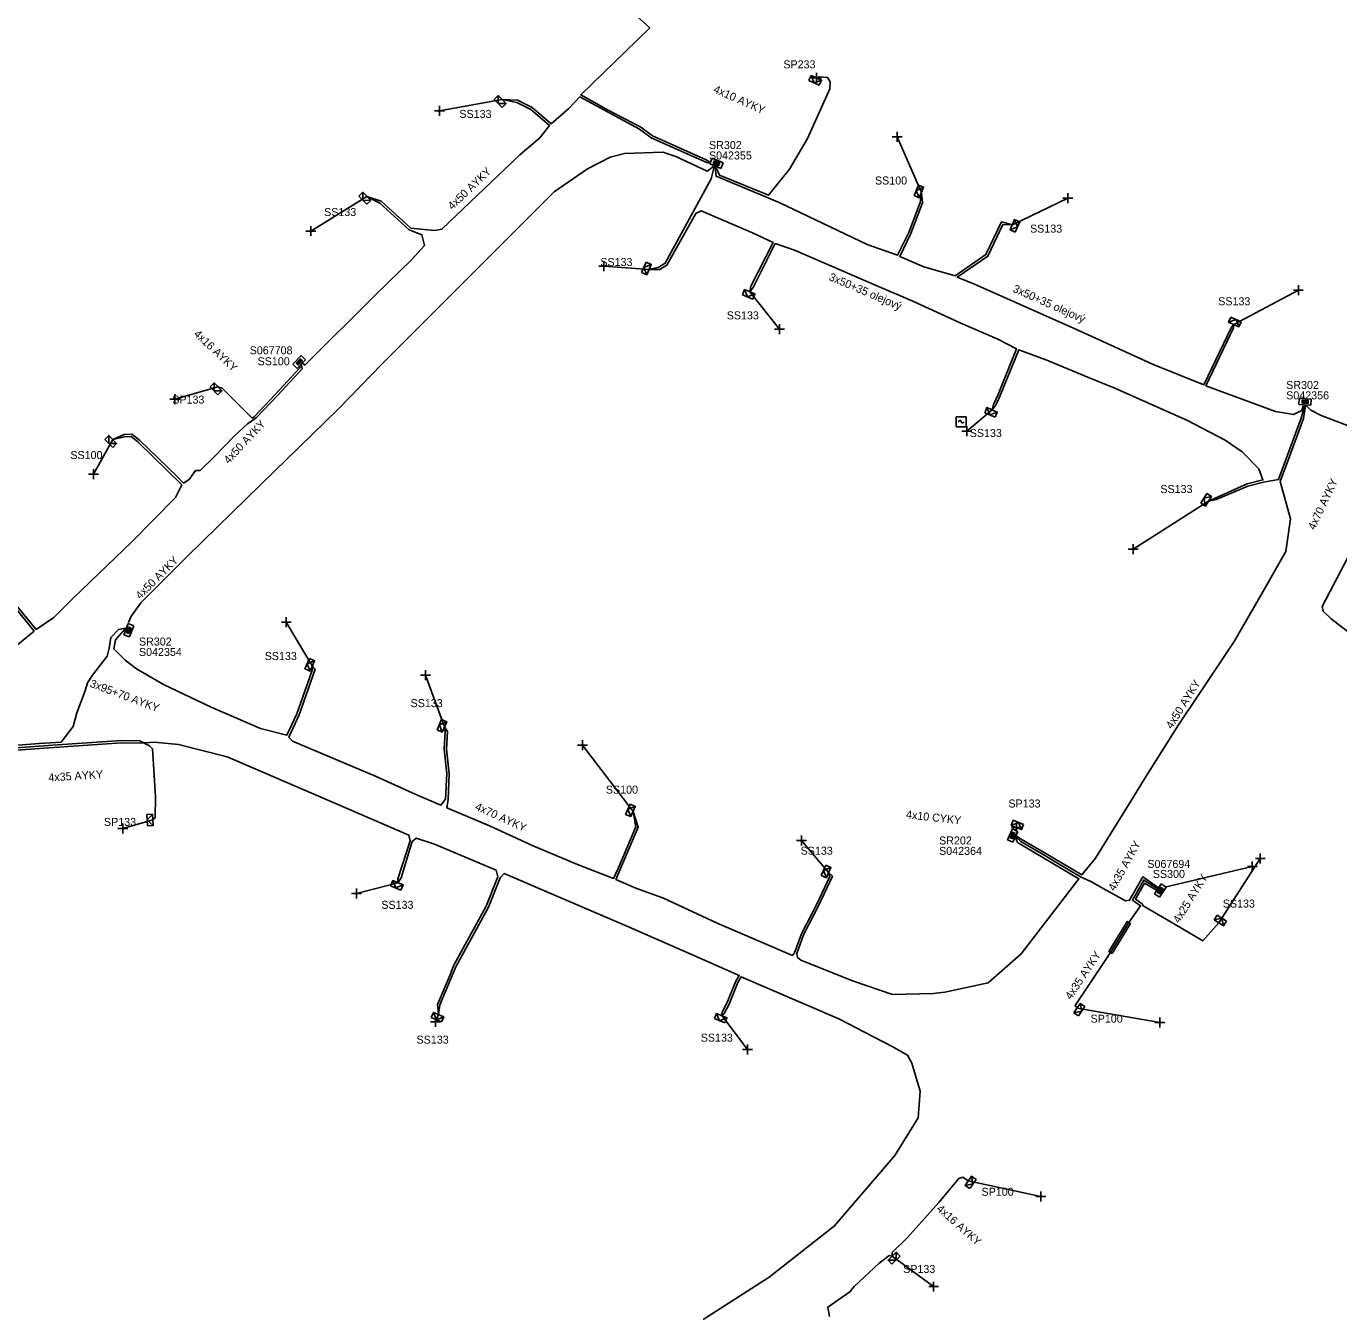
# Model space of a CAD drawing. Extents: x -748492 to -735633, y -1146251 to -1139940.
# Drawn here: x -736525.5 to -736361.6, y -1144461 to -1144300.4 of the extents above; entities that cross this region are included whole.
import ezdxf

# ---------------------------------------------------------------- set-up
doc = ezdxf.new("R2010")
doc.units = 0
for name, color, linetype in [('Vrstva 1', 7, 'Continuous'), ('Vrstva 20', 7, 'Continuous'), ('Vrstva 28', 7, 'Continuous'), ('Vrstva 29', 7, 'Continuous'), ('Vrstva 30', 7, 'Continuous'), ('Vrstva 31', 7, 'Continuous'), ('Vrstva 33', 7, 'Continuous'), ('Vrstva 34', 7, 'Continuous'), ('Vrstva 5', 7, 'Continuous'), ('Vrstva 52', 7, 'Continuous'), ('Vrstva 54', 7, 'Continuous'), ('Vrstva 59', 7, 'Continuous'), ('Vrstva 6', 7, 'Continuous'), ('Vrstva 8', 7, 'Continuous'), ('Vrstva 9', 7, 'Continuous')]:
    doc.layers.add(name, color=color, linetype=linetype)

# ---------------------------------------------------------------- blocks, each defined once
blk = doc.blocks.new('NN800')
at = {"layer": 'Vrstva 1'}
for points in [[(-0.44, 0.44), (0.44, -0.44)], [(-0.44, -0.44), (0.44, 0.44)]]:
    blk.add_lwpolyline(points, dxfattribs=at)
blk = doc.blocks.new('NN620')
at = {"layer": 'Vrstva 8'}
for points in [[(0.75, 0), (-0.75, 0)], [(-0.75, 0), (-0.75, -0.75)], [(0.75, -0.75), (0.75, 0)], [(-0.75, -0.75), (0.75, -0.75)], [(0.37, -0.18), (-0.38, -0.18)], [(-0.38, -0.18), (-0.38, -0.56)], [(-0.38, -0.56), (0.37, -0.56)], [(0.32, -0.23), (-0.33, -0.23)], [(-0.33, -0.23), (-0.33, -0.51)], [(-0.33, -0.51), (0.32, -0.51)], [(0.27, -0.27), (-0.28, -0.27)], [(-0.28, -0.27), (-0.28, -0.46)], [(-0.28, -0.46), (0.27, -0.46)], [(0.23, -0.32), (-0.23, -0.32)], [(-0.23, -0.32), (-0.23, -0.42)], [(-0.23, -0.42), (0.23, -0.42)], [(-0.19, -0.37), (0.19, -0.37)], [(0.23, -0.42), (0.23, -0.32)], [(0.27, -0.46), (0.27, -0.27)], [(0.32, -0.51), (0.32, -0.23)], [(0.37, -0.56), (0.37, -0.18)]]:
    blk.add_lwpolyline(points, dxfattribs=at)
blk = doc.blocks.new('NN630')
at = {"layer": 'Vrstva 9'}
for points in [[(0, -0.7), (-0.7, 0)], [(-0.7, -0.7), (-0.7, 0), (0.7, 0), (0.7, -0.7)], [(-0.7, -0.7), (0.7, -0.7)], [(0, -0.7), (0.7, 0)]]:
    blk.add_lwpolyline(points, dxfattribs=at)
blk = doc.blocks.new('NN740')
at = {"layer": 'Vrstva 1'}
for points in [[(0.62, 0.62), (-0.63, 0.62)], [(-0.63, 0.62), (-0.63, -0.63)], [(0, 0), (0, 0.01), (0, 0.03), (-0.01, 0.05), (-0.01, 0.06), (-0.02, 0.08), (-0.03, 0.09), (-0.04, 0.1), (-0.05, 0.11), (-0.06, 0.12), (-0.08, 0.13), (-0.09, 0.14), (-0.11, 0.14), (-0.12, 0.15), (-0.14, 0.15), (-0.15, 0.15), (-0.17, 0.15), (-0.18, 0.15), (-0.2, 0.15), (-0.21, 0.14), (-0.23, 0.13), (-0.24, 0.12), (-0.26, 0.11), (-0.27, 0.1), (-0.28, 0.09), (-0.29, 0.08), (-0.29, 0.06), (-0.3, 0.05), (-0.3, 0.03), (-0.31, 0.02), (-0.31, 0), (-0.31, 0)], [(0.62, -0.63), (0.62, 0.62)], [(-0.63, -0.63), (0.62, -0.63)], [(0, 0), (0, -0.02), (0, -0.03), (0.01, -0.05), (0.01, -0.06), (0.02, -0.08), (0.03, -0.09), (0.04, -0.1), (0.05, -0.11), (0.06, -0.12), (0.07, -0.13), (0.09, -0.14), (0.1, -0.15), (0.12, -0.15), (0.13, -0.15), (0.15, -0.15), (0.16, -0.15), (0.18, -0.15), (0.19, -0.15), (0.21, -0.14), (0.22, -0.14), (0.24, -0.13), (0.25, -0.12), (0.26, -0.11), (0.27, -0.09), (0.28, -0.08), (0.29, -0.07), (0.29, -0.05), (0.3, -0.04), (0.3, -0.02), (0.3, -0.01), (0.3, -0.01)]]:
    blk.add_lwpolyline(points, dxfattribs=at)

msp = doc.modelspace()

# ---------------------------------------------------------------- linework, layer by layer
at = {"layer": 'Vrstva 20'}
msp.add_lwpolyline([(-736389.88, -1144416.27), (-736390.3, -1144416.01), (-736388.01, -1144412.26), (-736387.59, -1144412.52)], close=True, dxfattribs=at)
at = {"layer": 'Vrstva 5'}
for points in [[(-736440.21, -1144317.36), (-736440.6, -1144317.09), (-736447.33, -1144314.09), (-736448.79, -1144313.02), (-736452.94, -1144310.85), (-736456.27, -1144308.99), (-736450.7, -1144303.56), (-736447.65, -1144300.62), (-736452.08, -1144296.64)], [(-736491.06, -1144342.47), (-736490.75, -1144342.74), (-736481.89, -1144333.95), (-736477.42, -1144329.58), (-736475.81, -1144327.82), (-736476.12, -1144326.48), (-736477.71, -1144325.85), (-736481.37, -1144322.52), (-736483, -1144321.67), (-736481.21, -1144322.26), (-736477.51, -1144325.63), (-736474.55, -1144325.92), (-736473.63, -1144325.79), (-736463.89, -1144316.47), (-736461.38, -1144314.35), (-736460.17, -1144312.82), (-736462.51, -1144310.83), (-736464.27, -1144309.96), (-736466.1, -1144309.57), (-736464.19, -1144309.66), (-736462.35, -1144310.57), (-736459.97, -1144312.6), (-736457.75, -1144310.68), (-736456.41, -1144309.25), (-736448.95, -1144313.28), (-736447.49, -1144314.35), (-736440.74, -1144317.35), (-736440.29, -1144317.54)], [(-736439.71, -1144317.93), (-736440.5, -1144318.51), (-736444.39, -1144316.69), (-736446.01, -1144316.16), (-736450.82, -1144316.33), (-736452.62, -1144316.77), (-736455.42, -1144318.25), (-736459.6, -1144321.09), (-736467.51, -1144329.02), (-736481.04, -1144342.55), (-736486.6, -1144348.27), (-736496.25, -1144357.68), (-736505.35, -1144366.59), (-736511.22, -1144372.44), (-736512.5, -1144374.21), (-736512.77, -1144374.92)], [(-736439.59, -1144317.99), (-736439.99, -1144319.5), (-736445.73, -1144330.03), (-736446.51, -1144330.52), (-736447.75, -1144330.82), (-736446.41, -1144330.8), (-736445.51, -1144330.25), (-736441.89, -1144323.81), (-736441.25, -1144323.47), (-736434.82, -1144326.24), (-736432.24, -1144327.43), (-736435.02, -1144332.87), (-736435.17, -1144333.59), (-736434.7, -1144332.99), (-736431.98, -1144327.57), (-736429.56, -1144328.39), (-736419.36, -1144332.81), (-736414.8, -1144334.76), (-736408.79, -1144337.53), (-736404.19, -1144339.51), (-736401.85, -1144340.71), (-736404.15, -1144346.43), (-736404.72, -1144347.67), (-736404.89, -1144348.34), (-736404.37, -1144347.66), (-736403.87, -1144346.55), (-736401.57, -1144340.83), (-736398.06, -1144342.15), (-736392.85, -1144344.32), (-736389.55, -1144345.65), (-736380.49, -1144349.68), (-736375.78, -1144352.14), (-736373.64, -1144353.6), (-736371.56, -1144355.73), (-736371.06, -1144357.09), (-736373.04, -1144357.59), (-736377.84, -1144359.77), (-736376.88, -1144359.54), (-736372.94, -1144357.87), (-736370.98, -1144357.39), (-736369.11, -1144357.06), (-736366.28, -1144349.39), (-736365.88, -1144347.85)], [(-736439.47, -1144318.04), (-736439.37, -1144319.16), (-736431.51, -1144322.44), (-736420.48, -1144327.7), (-736416.69, -1144329.03), (-736415.31, -1144326.2), (-736413.87, -1144322.42), (-736413.72, -1144321.19), (-736413.57, -1144322.48), (-736415.03, -1144326.32), (-736416.42, -1144329.17), (-736413.43, -1144330.46), (-736409.5, -1144331.59), (-736405.66, -1144328.95), (-736403.72, -1144324.87), (-736402.36, -1144325.21), (-736403.54, -1144325.19), (-736405.42, -1144329.15), (-736409.24, -1144331.77), (-736407.08, -1144332.65), (-736394.34, -1144338.32), (-736384.87, -1144342.64), (-736378.44, -1144345.2), (-736374.99, -1144338.03), (-736374.7, -1144337.68), (-736374.74, -1144338.11), (-736378.18, -1144345.34), (-736369.48, -1144348.55), (-736367.25, -1144348.92), (-736366.18, -1144348.42), (-736366.01, -1144347.84)], [(-736514.75, -1144352.04), (-736513.33, -1144351.43), (-736512.34, -1144351.39), (-736511.41, -1144352.12), (-736506.69, -1144356.65), (-736505.9, -1144357.5), (-736505.21, -1144357.04), (-736504.4, -1144355.92), (-736503.83, -1144355.9), (-736502.16, -1144354.28), (-736499.49, -1144351.56), (-736497.89, -1144350.1), (-736496.82, -1144349.36), (-736494.14, -1144346.49), (-736491.06, -1144343.22), (-736491.19, -1144342.63)], [(-736401.82, -1144401.62), (-736401.26, -1144401.96), (-736398.16, -1144403.77), (-736393.68, -1144406.44), (-736391.97, -1144404.35), (-736387.56, -1144397.22), (-736385.84, -1144394.45), (-736381.61, -1144387.69), (-736378.96, -1144383.76), (-736374.64, -1144377.3), (-736371.56, -1144371.96), (-736368.18, -1144366.03), (-736367.61, -1144361.94), (-736368.91, -1144357.3), (-736367.84, -1144354.5), (-736365.98, -1144349.43), (-736365.75, -1144347.85)], [(-736365.62, -1144347.86), (-736365.07, -1144348.39), (-736363.8, -1144349.06), (-736359.62, -1144350.63), (-736354.85, -1144352.88), (-736353.13, -1144352.91), (-736352.44, -1144352.02), (-736351.83, -1144350.9), (-736350.53, -1144349.56), (-736349.96, -1144349.5)], [(-736526.82, -1144372.73), (-736524.33, -1144375.78), (-736522.1, -1144374.28), (-736519.75, -1144371.93), (-736512.32, -1144364.8), (-736506.91, -1144359.28), (-736506.12, -1144357.7), (-736511.61, -1144352.34), (-736512.44, -1144351.69), (-736513.27, -1144351.73), (-736514.75, -1144352.04)], [(-736528.43, -1144379.15), (-736524.57, -1144375.98), (-736527.01, -1144372.97)], [(-736513.19, -1144375.63), (-736514.02, -1144375.78), (-736514.97, -1144376.79), (-736515.21, -1144378.1), (-736515.44, -1144379.11), (-736517.28, -1144381.47), (-736517.9, -1144382.45), (-736518.19, -1144383.45), (-736519.23, -1144386.21), (-736519.68, -1144387.88), (-736521.2, -1144389.86), (-736523.95, -1144390.03), (-736529.77, -1144390.49), (-736531.34, -1144391.33), (-736533.26, -1144392.69), (-736535.8, -1144394.49), (-736538.4, -1144396.09), (-736545.61, -1144401.24), (-736547.24, -1144402.4), (-736548.21, -1144402.26), (-736548.67, -1144401.65), (-736551.08, -1144398), (-736551.94, -1144397.36)], [(-736513.23, -1144375.75), (-736514.41, -1144377.07), (-736514.62, -1144378.21), (-736513.18, -1144379.6), (-736511.77, -1144380.69), (-736508.41, -1144382.64), (-736502.44, -1144385.48), (-736496.3, -1144388.13), (-736492.98, -1144388.98), (-736491.75, -1144386.33), (-736490.5, -1144382.77), (-736489.78, -1144380.74), (-736489.81, -1144380.33), (-736489.46, -1144380.72), (-736491.47, -1144386.45), (-736492.76, -1144389.25), (-736492.28, -1144389.72), (-736481.83, -1144394.16), (-736476.87, -1144396.39), (-736473.74, -1144397.73), (-736473.16, -1144396.99), (-736473.01, -1144393.77), (-736473.33, -1144390.75), (-736473.22, -1144388.57), (-736473.3, -1144387.95), (-736472.92, -1144388.53), (-736473.03, -1144390.75), (-736472.71, -1144393.77), (-736472.86, -1144397.01), (-736473.01, -1144398.06), (-736467.66, -1144400.32), (-736462.13, -1144402.85), (-736456.69, -1144405.13), (-736452.18, -1144406.88), (-736451.59, -1144405.66), (-736449.41, -1144400.45), (-736449.75, -1144398.52), (-736449.09, -1144400.47), (-736451.88, -1144407), (-736449.39, -1144408.11), (-736445.96, -1144409.34), (-736439.23, -1144412.46), (-736429.84, -1144416.49), (-736429.56, -1144416.16), (-736428.71, -1144413.8), (-736426.84, -1144410.17), (-736425.15, -1144406.63), (-736425.31, -1144406.15), (-736424.81, -1144406.61), (-736426.58, -1144410.31), (-736428.43, -1144413.92), (-736429.28, -1144416.26), (-736429.18, -1144416.77), (-736428.77, -1144417.09), (-736422.19, -1144419.73), (-736417.34, -1144421.39), (-736412.25, -1144421.25), (-736410.79, -1144421.08), (-736405.37, -1144419.91), (-736401.25, -1144416.31), (-736394.05, -1144406.92), (-736401.7, -1144402.38), (-736401.93, -1144401.85)], [(-736529.6, -1144391.08), (-736523.91, -1144390.63), (-736519.08, -1144390.33), (-736513.63, -1144389.94), (-736511.36, -1144389.99), (-736509.56, -1144389.86), (-736506.52, -1144390.14), (-736500.44, -1144391.68), (-736486.98, -1144397.48), (-736477.75, -1144401.47), (-736477.6, -1144402.19), (-736479.11, -1144406.92), (-736479.12, -1144407.42), (-736478.73, -1144406.82), (-736477.32, -1144402.27), (-736476.83, -1144401.84), (-736474.53, -1144402.6), (-736470, -1144404.5), (-736466.83, -1144405.86), (-736466.62, -1144406.67), (-736468.1, -1144410.34), (-736472.16, -1144417.8), (-736472.57, -1144418.92), (-736474.17, -1144422.63), (-736474.03, -1144423.89), (-736473.87, -1144422.69), (-736471.88, -1144417.92), (-736467.82, -1144410.46), (-736466.34, -1144406.79), (-736465.84, -1144406.26), (-736459.35, -1144409.05), (-736450.33, -1144412.94), (-736441.84, -1144416.65), (-736436.48, -1144419), (-736436.91, -1144419.73), (-736438.02, -1144422.46), (-736438.61, -1144423.59), (-736438.66, -1144424.02), (-736438.36, -1144423.75), (-736437.74, -1144422.58), (-736436.64, -1144419.87), (-736436.22, -1144419.16), (-736429.07, -1144422.24), (-736424.04, -1144424.42), (-736417.38, -1144427.88), (-736415.47, -1144428.96), (-736414.9, -1144429.96), (-736413.88, -1144433.46), (-736414.12, -1144436.79), (-736417.02, -1144441.51), (-736424.56, -1144450.29), (-736432.75, -1144456.69), (-736440.97, -1144461.98)], [(-736401.87, -1144401.74), (-736401.29, -1144402.27), (-736398.32, -1144404.03), (-736396.94, -1144404.83), (-736393.84, -1144406.7), (-736392.54, -1144407.28), (-736390.64, -1144408.33), (-736388.22, -1144409.67), (-736387.71, -1144409.61), (-736386.07, -1144406.67), (-736384.09, -1144408.05)], [(-736425.19, -1144461.6), (-736425.41, -1144460.44), (-736422.66, -1144458.54), (-736422.13, -1144457.86), (-736419.03, -1144454.97), (-736417.76, -1144453.99), (-736417.38, -1144454.07)]]:
    msp.add_lwpolyline(points, dxfattribs=at)
at = {"layer": 'Vrstva 52'}
for points in [[(-736439.35, -1144318.09), (-736438.96, -1144319.01), (-736432.81, -1144321.51), (-736430.19, -1144318.29), (-736427.94, -1144314.45), (-736425.18, -1144308.25), (-736425.12, -1144307.36), (-736425.44, -1144306.81), (-736426.44, -1144306.73), (-736426.84, -1144306.86)], [(-736491.34, -1144342.74), (-736491.36, -1144343.1), (-736494.46, -1144346.41), (-736497.04, -1144349.16), (-736497.33, -1144349.38), (-736501.06, -1144345.65), (-736501.6, -1144345.48)], [(-736356.42, -1144364.46), (-736356.78, -1144363.34), (-736357.23, -1144362.86), (-736357.91, -1144362.75), (-736358.82, -1144363.64), (-736359.89, -1144365.75), (-736363.66, -1144372.92), (-736363.55, -1144373.51), (-736362.55, -1144374.43), (-736359.45, -1144376.81), (-736357.38, -1144378.42)], [(-736552.04, -1144397.44), (-736551.32, -1144398.19), (-736550.07, -1144400.08), (-736548.9, -1144401.84), (-736548.25, -1144402.56), (-736547.17, -1144402.71), (-736545.44, -1144401.49), (-736541.24, -1144398.5), (-736538.23, -1144396.34), (-736535.62, -1144394.73), (-736534.61, -1144393.97), (-736531.18, -1144391.58), (-736529.68, -1144390.78), (-736521.65, -1144390.2), (-736513.63, -1144389.64), (-736511.36, -1144389.69), (-736510.14, -1144390.3), (-736509.78, -1144390.68), (-736509.4, -1144396.65), (-736509.45, -1144399.3), (-736509.74, -1144399.56)], [(-736401.89, -1144400.76), (-736401.86, -1144400.52)], [(-736384.2, -1144408.2), (-736385.95, -1144407.08), (-736387.36, -1144409.59), (-736386.33, -1144410.29), (-736387.8, -1144412.39), (-736390.09, -1144416.14), (-736394.53, -1144422.75), (-736394.27, -1144423.08)], [(-736384.28, -1144408.4), (-736385.83, -1144407.48), (-736386.96, -1144409.49), (-736386.16, -1144410.05), (-736386.02, -1144410.31), (-736382.03, -1144412.62), (-736378.58, -1144414.67), (-736376.56, -1144412.42)], [(-736417.38, -1144454.07), (-736417.38, -1144453.63), (-736415.47, -1144451.76), (-736411.56, -1144447.36), (-736409.05, -1144444.37), (-736408.54, -1144444.21), (-736407.87, -1144444.66)]]:
    msp.add_lwpolyline(points, dxfattribs=at)
at = {"layer": 'Vrstva 59'}
for points in [[(-736466.1, -1144309.57), (-736473.94, -1144311)], [(-736413.72, -1144321.19), (-736416.75, -1144314.25)], [(-736483, -1144321.67), (-736490, -1144326)], [(-736402.36, -1144325.21), (-736395.44, -1144321.88)], [(-736447.75, -1144330.82), (-736453.38, -1144330.38)], [(-736435.17, -1144333.59), (-736431.44, -1144338.25)], [(-736374.7, -1144337.68), (-736366.63, -1144333.38)], [(-736501.6, -1144345.48), (-736507, -1144347)], [(-736404.89, -1144348.34), (-736408.06, -1144351)], [(-736514.75, -1144352.04), (-736517.13, -1144356.38)], [(-736377.84, -1144359.77), (-736387.25, -1144365.75)], [(-736489.81, -1144380.33), (-736493.06, -1144374.88)], [(-736473.3, -1144387.95), (-736475.69, -1144381.5)], [(-736449.75, -1144398.52), (-736456.06, -1144390.25)], [(-736509.74, -1144399.56), (-736513.5, -1144400.63)], [(-736425.31, -1144406.15), (-736428.69, -1144402.13)], [(-736376.56, -1144412.42), (-736371.38, -1144404.38)], [(-736383.31, -1144407.99), (-736372.38, -1144405.38)], [(-736479.12, -1144407.42), (-736484.31, -1144408.75)], [(-736474.03, -1144423.89), (-736474.42, -1144424.81)], [(-736438.66, -1144424.02), (-736435.44, -1144428.25)], [(-736394.27, -1144423.08), (-736383.94, -1144424.88)], [(-736407.87, -1144444.66), (-736398.81, -1144446.63)], [(-736417.38, -1144454.07), (-736412.19, -1144457.88)]]:
    msp.add_lwpolyline(points, dxfattribs=at)

# ---------------------------------------------------------------- block references
at = {"layer": 'Vrstva 28'}
for p, rotation in [((-736439.48, -1144317.89), 157.03459726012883), ((-736491.19, -1144342.63), -135.19991385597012), ((-736365.81, -1144347.72), 176.66485850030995), ((-736513.09, -1144375.74), 68.62937781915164), ((-736401.99, -1144401.68), -114.8399083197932), ((-736384.2, -1144408.2), 56.495877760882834)]:
    msp.add_blockref('NN620', p, dxfattribs=dict(at, rotation=rotation))
at = {"layer": 'Vrstva 31'}
for p, rotation in [((-736426.84, -1144306.86), -24.028288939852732), ((-736466.1, -1144309.57), -45.436897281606), ((-736413.72, -1144321.19), -112.43461664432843), ((-736483, -1144321.67), -45.90858057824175), ((-736402.36, -1144325.21), 66.33653611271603), ((-736447.75, -1144330.82), -113.24059168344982), ((-736435.17, -1144333.59), -22.743036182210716), ((-736374.7, -1144337.68), 155.94560281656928), ((-736501.6, -1144345.48), -45.16283061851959), ((-736404.89, -1144348.34), -23.049180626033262), ((-736514.75, -1144352.04), -44.92818887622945), ((-736377.84, -1144359.77), -122.49232773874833), ((-736489.81, -1144380.33), -113.41980828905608), ((-736473.3, -1144387.95), -113.30655000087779), ((-736449.75, -1144398.52), -113.06151938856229), ((-736509.74, -1144399.56), -85.89018609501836), ((-736401.86, -1144400.52), 157.5205666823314), ((-736425.31, -1144406.15), -113.31839723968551), ((-736479.12, -1144407.42), -22.537400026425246), ((-736376.56, -1144412.42), 146.84634438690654), ((-736474.03, -1144423.89), -22.80708885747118), ((-736438.66, -1144424.02), -23.224977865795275), ((-736394.27, -1144423.08), 56.22091111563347), ((-736407.87, -1144444.66), 55.8356028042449), ((-736417.38, -1144454.07), 43.96589167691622)]:
    msp.add_blockref('NN630', p, dxfattribs=dict(at, rotation=rotation))
at = {"layer": 'Vrstva 34'}
for name, p, rotation in [('NN800', (-736426.84, -1144306.86), 45), ('NN800', (-736473.94, -1144311), 44.99999995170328), ('NN800', (-736416.75, -1144314.25), 45), ('NN800', (-736395.44, -1144321.88), 44.99999995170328), ('NN800', (-736490, -1144326), 45), ('NN800', (-736453.38, -1144330.38), 45), ('NN800', (-736366.63, -1144333.38), 45), ('NN800', (-736431.44, -1144338.25), 44.99999995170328), ('NN800', (-736507, -1144347), 45), ('NN740', (-736408.75, -1144349.82), 0.08500856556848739), ('NN800', (-736408.06, -1144351), 45), ('NN800', (-736517.13, -1144356.38), 45), ('NN800', (-736387.25, -1144365.75), 45), ('NN800', (-736493.06, -1144374.88), 45), ('NN800', (-736475.69, -1144381.5), 44.99999995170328), ('NN800', (-736456.06, -1144390.25), 45), ('NN800', (-736513.5, -1144400.63), 45), ('NN800', (-736401.86, -1144400.52), 45), ('NN800', (-736428.69, -1144402.13), 44.99999995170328), ('NN800', (-736371.38, -1144404.38), 45), ('NN800', (-736372.38, -1144405.38), 45), ('NN800', (-736484.31, -1144408.75), 45), ('NN800', (-736474.42, -1144424.81), 45), ('NN800', (-736383.94, -1144424.88), 44.99999995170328), ('NN800', (-736435.44, -1144428.25), 44.99999995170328), ('NN800', (-736398.81, -1144446.63), 45), ('NN800', (-736412.19, -1144457.88), 44.99999995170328)]:
    msp.add_blockref(name, p, dxfattribs=dict(at, rotation=rotation))

# ---------------------------------------------------------------- texts
at = {"layer": 'Vrstva 29'}
for s, p in [('S042355', (-736440.26, -1144317.06)), ('S067708', (-736497.64, -1144341.4)), ('S042356', (-736368.15, -1144347.03)), ('S042354', (-736511.47, -1144379.09)), ('S042364', (-736411.51, -1144403.94)), ('S067694', (-736385.49, -1144405.57))]:
    msp.add_text(s, height=1, dxfattribs=at).set_placement(p)
at = {"layer": 'Vrstva 30'}
for s, p in [('SR302', (-736440.26, -1144315.76)), ('SS100', (-736496.65, -1144342.77)), ('SR302', (-736368.15, -1144345.73)), ('SR302', (-736511.47, -1144377.79)), ('SR202', (-736411.51, -1144402.64)), ('SS300', (-736384.81, -1144406.82))]:
    msp.add_text(s, height=1, dxfattribs=at).set_placement(p)
at = {"layer": 'Vrstva 33'}
for s, p in [('SP233', (-736430.97, -1144305.68)), ('SS133', (-736471.44, -1144311.87)), ('SS100', (-736419.52, -1144320.19)), ('SS133', (-736488.34, -1144324.13)), ('SS133', (-736400.15, -1144326.2)), ('SS133', (-736453.83, -1144330.37)), ('SS133', (-736376.64, -1144335.28)), ('SS133', (-736438.04, -1144337.04)), ('SP133', (-736507.31, -1144347.56)), ('SS133', (-736407.68, -1144351.74)), ('SS100', (-736520.04, -1144354.49)), ('SS133', (-736383.87, -1144358.73)), ('SS133', (-736495.76, -1144379.6)), ('SS133', (-736477.54, -1144385.48)), ('SS100', (-736453.14, -1144396.29)), ('SP133', (-736402.85, -1144398.02)), ('SP133', (-736515.84, -1144400.32)), ('SS133', (-736428.81, -1144403.92)), ('SS133', (-736481.19, -1144410.68)), ('SS133', (-736376.07, -1144410.52)), ('SP100', (-736392.59, -1144424.9)), ('SS133', (-736476.79, -1144427.52)), ('SS133', (-736441.29, -1144427.27)), ('SP100', (-736406.21, -1144446.53)), ('SP133', (-736416, -1144456.17))]:
    msp.add_text(s, height=1, dxfattribs=at).set_placement(p)
at = {"layer": 'Vrstva 54'}
for s, rotation, p in [('4x10 AYKY', 336.003, (-736439.79, -1144308.64)), ('4x16 AYKY', 316.807, (-736504.71, -1144338.97)), ('4x35 AYKY', 3.642, (-736522.75, -1144394.78)), ('4x10 CYKY', 353.606, (-736415.68, -1144399.36)), ('4x25 AYKY', 58.108, (-736381.52, -1144412.55)), ('4x35 AYKY', 56.142, (-736395.03, -1144422.1)), ('4x16 AYKY', 318.375, (-736411.9, -1144448.28))]:
    msp.add_text(s, height=1, rotation=rotation, dxfattribs=at).set_placement(p)
at = {"layer": 'Vrstva 6'}
for s, rotation, p in [('4x50 AYKY', 43.738, (-736472.32, -1144323.41)), ('3x50+35 olejový', 336.847, (-736425.37, -1144332.1)), ('3x50+35 olejový', 336.008, (-736402.39, -1144333.56)), ('4x50 AYKY', 46.839, (-736500.26, -1144355.16)), ('4x70 AYKY', 64.747, (-736364.58, -1144363.42)), ('4x50 AYKY', 44.902, (-736511.3, -1144372.08)), ('3x95+70 AYKY', 339.353, (-736517.68, -1144382.91)), ('4x50 AYKY', 57.964, (-736382.42, -1144388.28)), ('4x70 AYKY', 335.416, (-736469.57, -1144398.25)), ('4x35 AYKY', 61.074, (-736389.59, -1144408.53))]:
    msp.add_text(s, height=1, rotation=rotation, dxfattribs=at).set_placement(p)

doc.saveas('drawing.dxf')
